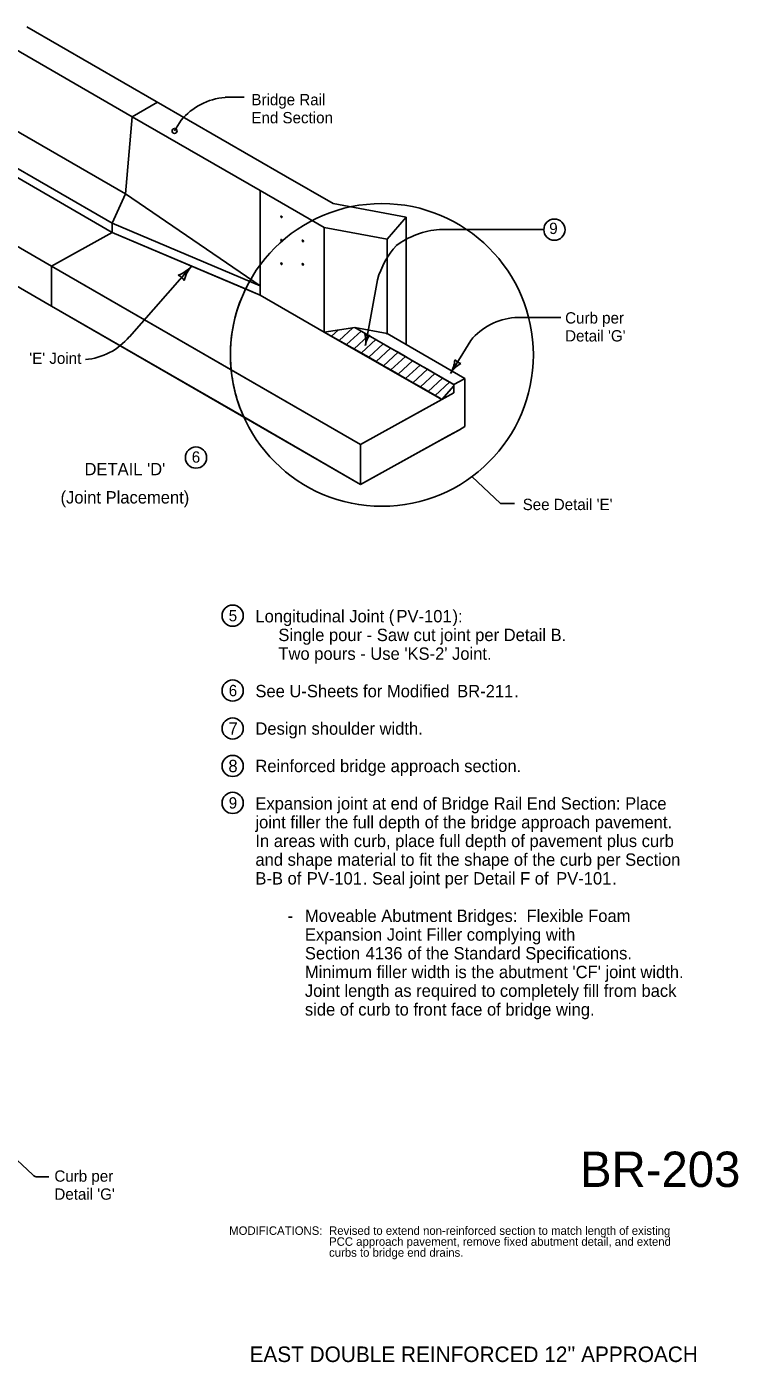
# Model space of a CAD drawing. Extents: x 5546 to 81668, y 3174 to 15999.
# Drawn here: x 19394 to 20400, y 12314 to 14204 of the extents above; entities that cross this region are included whole.
import ezdxf

# ---------------------------------------------------------------- set-up
doc = ezdxf.new("R2010")
doc.units = 0
for name, color, linetype in [('PC_REBAR', 7, 'Continuous'), ('PS_BOLT', 7, 'Continuous'), ('PS_CONST', 7, 'Continuous'), ('PS_DIM', 7, 'Continuous'), ('SheetAddenda', 7, 'Continuous'), ('tdCoLegendTitle', 7, 'Continuous'), ('tdCoShieldUsRte', 7, 'Continuous')]:
    doc.layers.add(name, color=color, linetype=linetype)

msp = doc.modelspace()

# ---------------------------------------------------------------- linework, layer by layer
at = {"layer": 'PC_REBAR'}
msp.add_circle((19602.7, 14056.8), 3.54, dxfattribs=at)
at = {"layer": 'PS_CONST'}
for centre, radius, start, end in [((19956.7, 13735.5), 42.5, 328.7108, 356.7833), ((20029.3, 13691.4), 42.5, 120.6383, 148.7108), ((20011.5, 13743.9), 16.4, 220.9775, 256.4442)]:
    msp.add_arc(centre, radius, start, end, dxfattribs=at)
at = {"layer": 'PS_DIM'}
for p, q in [((19393.7, 14204.4), (19759.7, 13993.1)), ((19542.8, 14076.9), (19357.8, 14183.7)), ((19674.2, 14104.5), (19701.1, 14104.5)), ((19533.4, 13967.8), (19348.4, 14074.6)), ((19723.8, 13972.4), (19542.8, 14076.9)), ((19602.7, 14056.8), (19612, 14072.1)), ((19514.5, 13926.4), (19329.5, 14033.2)), ((19759.7, 13993.1), (19827, 13954.2)), ((19723.8, 13972.4), (19723.8, 13824.5)), ((19814.4, 13920.1), (19723.8, 13972.4)), ((19827, 13954.2), (19930.2, 13934.9)), ((19930.2, 13934.9), (19930.2, 13754.8)), ((19514.5, 13913.3), (19428.7, 13865.7)), ((19514.5, 13913.3), (19428.7, 13865.7)), ((19703.2, 13833.3), (19514.5, 13913.3)), ((19723.8, 13824.5), (19514.5, 13913.3)), ((19814.4, 13920.1), (19814.4, 13772.2)), ((19814.4, 13920.1), (19903.3, 13903.5)), ((19977.6, 13917.5), (20125.1, 13917.5)), ((19903.3, 13770.3), (19903.3, 13903.5)), ((19428.7, 13865.7), (19428.7, 13809.1)), ((19682.8, 13719), (19428.7, 13865.7)), ((19428.7, 13865.7), (19428.7, 13809.1)), ((19428.7, 13865.7), (19682.8, 13719)), ((19428.7, 13865.7), (19865.9, 13613.3)), ((19627.2, 13866), (19538.8, 13765.7)), ((19889.8, 13846.3), (19872.6, 13753.3)), ((19723.8, 13824.5), (19703.2, 13833.3)), ((19814.4, 13772.2), (19723.8, 13824.5)), ((19814.4, 13772.2), (19723.8, 13824.5)), ((19428.7, 13809.1), (19865.9, 13556.7)), ((19428.7, 13809.1), (19700.6, 13652.1)), ((20083.8, 13792.9), (20149, 13792.9)), ((19857.7, 13778.9), (19814.4, 13772.2)), ((19857.7, 13778.9), (19814.4, 13772.2)), ((19877.6, 13736.6), (19814.4, 13772.2)), ((19814.4, 13772.2), (19814.4, 13772.2)), ((19814.4, 13772.2), (19877.6, 13736.6)), ((19977.3, 13679.1), (19814.4, 13772.2)), ((19980.9, 13677), (19814.4, 13772.2)), ((19814.4, 13772.2), (19814.4, 13772.2)), ((19834.7, 13775.3), (19824.9, 13766.3)), ((19854.9, 13778.4), (19835.5, 13760.4)), ((19866.7, 13773.7), (19846, 13754.5)), ((19877.1, 13767.6), (19856.6, 13748.6)), ((19898, 13755.6), (19857.7, 13778.9)), ((19903.3, 13770.3), (19857.7, 13778.9)), ((19857.7, 13778.9), (19898, 13755.6)), ((19997.8, 13698), (19857.7, 13778.9)), ((19857.7, 13778.9), (19903.3, 13770.3)), ((19887.6, 13761.6), (19867.2, 13742.7)), ((20013.5, 13706.7), (19903.3, 13770.3)), ((20013.5, 13706.7), (19903.3, 13770.3)), ((19993, 13713.5), (20021.6, 13760.5)), ((19877.6, 13736.6), (19898, 13755.6)), ((19898, 13755.6), (19877.6, 13736.6)), ((19898, 13755.6), (19877.6, 13736.6)), ((19888, 13730.6), (19908.4, 13749.6)), ((19908.4, 13749.6), (19888, 13730.6)), ((19908.4, 13749.6), (19888, 13730.6)), ((19908.4, 13749.6), (19898, 13755.6)), ((19898, 13755.6), (19908.4, 13749.6)), ((19898.4, 13724.6), (19918.8, 13743.6)), ((19918.8, 13743.6), (19898.4, 13724.6)), ((19918.8, 13743.6), (19898.4, 13724.6)), ((19918.8, 13743.6), (19908.4, 13749.6)), ((19908.4, 13749.6), (19918.8, 13743.6)), ((19929.2, 13737.6), (19918.8, 13743.6)), ((19918.8, 13743.6), (19929.2, 13737.6)), ((19877.6, 13736.6), (19888, 13730.6)), ((19888, 13730.6), (19898.4, 13724.6)), ((19898.4, 13724.6), (19908.8, 13718.6)), ((19908.8, 13718.6), (19929.2, 13737.6)), ((19929.2, 13737.6), (19908.8, 13718.6)), ((19929.2, 13737.6), (19908.8, 13718.6)), ((19939.5, 13731.6), (19919.4, 13713)), ((19929.6, 13706.6), (19950, 13725.6)), ((19950, 13725.6), (19929.6, 13706.6)), ((19950, 13725.6), (19929.6, 13706.6)), ((19960.4, 13719.6), (19950, 13725.6)), ((19950, 13725.6), (19960.4, 13719.6)), ((19682.8, 13719), (19865.9, 13613.3)), ((19865.9, 13613.3), (19682.8, 13719)), ((19908.8, 13718.6), (19929.6, 13706.6)), ((19929.6, 13706.6), (19940, 13700.6)), ((19940, 13700.6), (19960.4, 13719.6)), ((19960.4, 13719.6), (19940, 13700.6)), ((19960.4, 13719.6), (19940, 13700.6)), ((19970.9, 13713.5), (19950.5, 13694.5)), ((19981.9, 13707.2), (19961.5, 13688.2)), ((20013.5, 13706.7), (20005.6, 13702.3)), ((20005.6, 13702.3), (20013.5, 13706.7)), ((20013.5, 13706.7), (20005.6, 13702.3)), ((20013.5, 13638.4), (20013.5, 13706.7)), ((19865.9, 13613.3), (19997.8, 13686.3)), ((19940, 13700.6), (19950.5, 13694.5)), ((19950.5, 13694.5), (19971.2, 13682.6)), ((19971.2, 13682.6), (19991.6, 13701.5)), ((19991.6, 13701.5), (19971.2, 13682.6)), ((19991.6, 13701.5), (19971.2, 13682.6)), ((19980.9, 13677), (19997.8, 13696.1)), ((19997.8, 13696.1), (19980.9, 13677)), ((19980.9, 13677), (19997.8, 13696.1)), ((19997.8, 13686.3), (19980.9, 13677)), ((19980.9, 13677), (19997.8, 13686.3)), ((19997.8, 13698), (19991.6, 13701.5)), ((19991.6, 13701.5), (19997.8, 13698)), ((20005.6, 13702.3), (19997.8, 13698)), ((19997.8, 13698), (20005.6, 13702.3)), ((20005.6, 13702.3), (19997.8, 13698)), ((19997.8, 13696.1), (19997.8, 13698)), ((19997.8, 13686.3), (19997.8, 13698)), ((19997.8, 13686.3), (19997.8, 13696.1)), ((19865.9, 13613.3), (19980.9, 13677)), ((19980.9, 13677), (19865.9, 13613.3)), ((19971.2, 13682.6), (19977.3, 13679.1)), ((19980.9, 13677), (19977.3, 13679.1)), ((19977.3, 13679.1), (19980.9, 13677)), ((19700.6, 13652.1), (19865.9, 13556.7)), ((19970.4, 13614.5), (20005.6, 13634.1)), ((19990.5, 13625.7), (20005.6, 13634.1)), ((20005.6, 13634.1), (20013.5, 13638.4)), ((20013.5, 13638.4), (20005.6, 13634.1)), ((19865.9, 13556.7), (19990.5, 13625.7)), ((19865.9, 13556.7), (19865.9, 13613.3)), ((20023.4, 13567.7), (20063.8, 13529.7)), ((20063.8, 13529.7), (20083.6, 13529.7)), ((19365.1, 12614.3), (19402.3, 12579.4)), ((19409.1, 12576.7), (19425, 12576.7))]:
    msp.add_line(p, q, dxfattribs=at)
for points in [[(19542.8, 14076.9), (19578.6, 14097.6)], [(19514.5, 13913.3), (19514.5, 13926.4), (19533.4, 13967.8), (19542.8, 14076.9)], [(19514.5, 13913.3), (19329.5, 14020.1)], [(19243.7, 13972.5), (19428.7, 13865.7)], [(19514.5, 13926.4), (19723.8, 13837.6), (19533.4, 13967.8)], [(19903.3, 13903.5), (19930.2, 13934.9)], [(19428.7, 13809.1), (19243.7, 13915.9)], [(19514.5, 13913.3), (19428.7, 13865.7)], [(19428.7, 13809.1), (19428.7, 13865.7)], [(19814.4, 13772.2), (19814.4, 13772.2)], [(19903.3, 13770.3), (19902.5, 13769.9), (19903.3, 13770.3)], [(19898.4, 13724.6), (19888, 13730.6), (19877.6, 13736.6)], [(19929.6, 13706.6), (19908.8, 13718.6), (19898.4, 13724.6)], [(19950, 13725.6), (19939.5, 13731.6), (19929.2, 13737.6)], [(19929.2, 13737.6), (19939.5, 13731.6), (19950, 13725.6)], [(19977.3, 13679.1), (19971.2, 13682.6), (19950.5, 13694.5), (19940, 13700.6), (19929.6, 13706.6)], [(19991.6, 13701.5), (19981.9, 13707.2), (19960.4, 13719.6)], [(19960.4, 13719.6), (19981.9, 13707.2), (19991.6, 13701.5)], [(20013.5, 13706.7), (20013.5, 13638.4)], [(19997.8, 13698), (19997.8, 13696.1), (19997.8, 13686.3)], [(19865.9, 13556.7), (19970.4, 13614.5), (19990.5, 13625.7)]]:
    msp.add_lwpolyline(points, dxfattribs=at)
for centre, radius in [((19896, 13739.9), 214.2), ((20140, 13917.1), 15), ((19633, 13594.6), 15), ((19685, 13370.9), 15), ((19685, 13264.9), 15), ((19685, 13211.2), 15), ((19685, 13158.2), 15), ((19685, 13105.9), 15)]:
    msp.add_circle(centre, radius, dxfattribs=at)
for centre, radius, start, end in [((19681.9, 14013.7), 91, 94.8409, 140.1467), ((19986.5, 13800.3), 117.5, 94.3399, 126.627), ((20003.2, 13815.4), 117.5, 137.5971, 164.7195), ((19591, 13898.1), 48.4, 290.4433, 318.5158), ((19663.5, 13834), 48.4, 138.5158, 166.5883), ((19600.4, 13835.6), 18.7, 30.7825, 66.2492), ((19896, 13739.9), 214.2, 154.1687, 185.6063), ((19896, 13739.9), 214.2, 154.1687, 185.6063), ((20091.5, 13702.2), 91, 94.8409, 140.1467), ((19468.9, 13824), 91, 274.8409, 320.1467), ((19877.5, 13779.9), 12.5, 241.782, 277.2487), ((19840.9, 13759.2), 32.3, 349.5153, 17.5878), ((19904.3, 13747.5), 32.3, 141.4428, 169.5153), ((19896, 13739.9), 214.2, 185.6063, 204.2018), ((19896, 13739.9), 214.2, 185.6063, 204.2018), ((19409.1, 12586.7), 10, 226.7172, 270)]:
    msp.add_arc(centre, radius, start, end, dxfattribs=at)
for centre in [(19754, 13935.3), (19754, 13902.1), (19784.2, 13901.2), (19754, 13868.9), (19784.2, 13868)]:
    msp.add_ellipse(centre, major_axis=(0.67, -1.15), ratio=0.57735, dxfattribs=at)

# ---------------------------------------------------------------- texts
at = {"layer": 'PS_BOLT'}
for s, height, p in [('6', 16, (19627.1, 13587.4)), ('(Joint Placement)', 17.5, (19441.5, 13529.6))]:
    msp.add_text(s, height=height, dxfattribs=at).set_placement(p)
at = {"layer": 'PS_DIM'}
for s, height, p in [('Bridge Rail ', 16, (19711.4, 14093.2)), ('End Section', 16, (19711.4, 14067.7)), ('Curb per', 16, (20155.2, 13784.3)), ("Detail 'G'", 16, (20155.2, 13758.9)), ("'E' Joint", 16, (19397.3, 13727.2)), ("DETAIL 'D'", 17.5, (19475.4, 13569.6)), ("See Detail 'E'", 16, (20095.1, 13520.3)), ('Curb per', 16, (19432.8, 12569.8)), ("Detail 'G'", 16, (19432.8, 12544.3))]:
    msp.add_text(s, height=height, dxfattribs=at).set_placement(p)
at = {"layer": 'SheetAddenda'}
for s, height, p in [('9', 16, (20132.7, 13911)), ('5', 16, (19679.4, 13362.9)), ('Longitudinal Joint (', 17.5, (19717.1, 13361.4)), ('PV-101', 17.5, (19916.6, 13361.4)), ('):', 17.5, (19995.9, 13361.4)), ('     Single pour - Saw cut joint per Detail B.', 17.5, (19717.1, 13334.9)), ("     Two pours - Use 'KS-2' Joint.", 17.5, (19717.1, 13308.4)), ('6', 16, (19679.4, 13256.9)), ('See U-Sheets for Modified ', 17.5, (19717.1, 13255.4)), ('BR-211', 17.5, (20002.5, 13255.4)), ('.', 17.5, (20083.1, 13255.4)), ('7', 17.5, (19679.1, 13202.4)), ('Design shoulder width.', 17.5, (19717.1, 13202.4)), ('8', 17.5, (19678.9, 13149.4)), ('Reinforced bridge approach section.', 17.5, (19717.1, 13149.4)), ('9', 16, (19679.4, 13097.9)), ('Expansion joint at end of Bridge Rail End Section: Place', 17.5, (19717.1, 13096.4)), ('joint filler the full depth of the bridge approach pavement.', 17.5, (19717.1, 13069.9)), ('In areas with curb, place full depth of pavement plus curb', 17.5, (19717.1, 13043.4)), ('and shape material to fit the shape of the curb per Section', 17.5, (19717.1, 13016.9)), ('B-B of ', 17.5, (19717.1, 12990.4)), ('PV-101', 17.5, (19789.7, 12990.4)), ('. Seal joint per Detail F of ', 17.5, (19869, 12990.4)), ('PV-101', 17.5, (20142.5, 12990.4)), ('.', 17.5, (20221.8, 12990.4)), ('Moveable Abutment Bridges:  Flexible Foam', 17.5, (19787.1, 12937.4)), ('       -', 17.5, (19717.1, 12937.4)), ('Expansion Joint Filler complying with ', 17.5, (19787.1, 12910.9)), ('Section ', 17.5, (19787.1, 12884.4)), ('4136', 17.5, (19873, 12884.4)), (' of the Standard Specifications.', 17.5, (19925.8, 12884.4)), ("Minimum filler width is the abutment 'CF' joint width.", 17.5, (19787.1, 12857.9)), ('Joint length as required to completely fill from back ', 17.5, (19787.1, 12831.4)), ('side of curb to front face of bridge wing.', 17.5, (19787.1, 12804.9))]:
    msp.add_text(s, height=height, dxfattribs=at).set_placement(p)
at = {"layer": 'tdCoLegendTitle'}
for s, height, p in [('BR-203', 50, (20176.3, 12562.4)), ('Revised to extend non-reinforced section to match length of existing ', 12, (19821.3, 12494.6)), ('curbs to bridge end drains.', 12, (19821.3, 12463.6)), ('PCC approach pavement, remove fixed abutment detail, and extend ', 12, (19821.3, 12479.1)), ("EAST DOUBLE REINFORCED 12'' APPROACH", 22, (19708.8, 12314.6))]:
    msp.add_text(s, height=height, dxfattribs=at).set_placement(p)
at = {"layer": 'tdCoShieldUsRte'}
msp.add_text('MODIFICATIONS:', height=12, dxfattribs=at).set_placement((19680, 12494.6))

doc.saveas('drawing.dxf')
